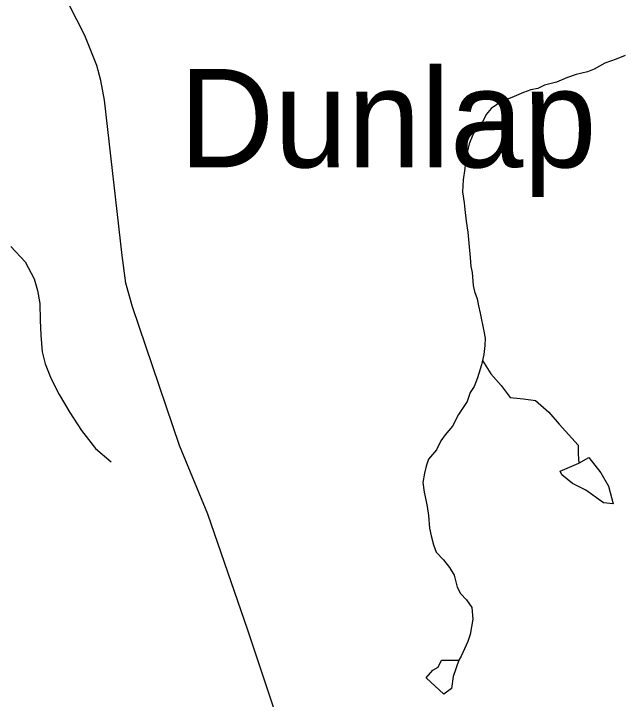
# Model space of a CAD drawing. Extents: x 0 to 34, y 0 to 22.
# Drawn here: x 2.892 to 3.382, y 19.73 to 20.28 of the extents above; entities that cross this region are included whole.
import ezdxf

# ---------------------------------------------------------------- set-up
doc = ezdxf.new("R2010")
doc.units = 0
for name, color, linetype in [('GM_X_County_Road', 7, 'Continuous'), ('GM_X_Minor_Lake', 7, 'Continuous'), ('GM_X_Minor_River', 7, 'Continuous'), ('GM_X_Unincorporated_Text', 7, 'Continuous')]:
    doc.layers.add(name, color=color, linetype=linetype)

msp = doc.modelspace()

# ---------------------------------------------------------------- linework, layer by layer
at = {"layer": 'GM_X_County_Road'}
msp.add_lwpolyline([(3.29284, 19.28987), (3.24187, 19.38373), (3.19405, 19.46941), (3.16152, 19.53179), (3.14395, 19.59345), (3.08002, 19.78523), (3.04799, 19.87833), (3.02524, 19.93351), (2.98757, 20.04453), (2.98244, 20.0637), (2.97932, 20.08578), (2.96513, 20.2103), (2.96238, 20.22608), (2.95906, 20.23808), (2.94936, 20.26224), (2.91043, 20.33888)], dxfattribs=at)
at = {"layer": 'GM_X_Minor_Lake'}
for points in [[(3.36531, 19.88758), (3.35109, 19.89775), (3.34055, 19.9029), (3.33196, 19.90992), (3.3305, 19.91299), (3.34538, 19.91923)], [(3.34538, 19.91923), (3.35352, 19.92392), (3.36315, 19.91156), (3.36938, 19.90079), (3.3729, 19.88666), (3.36531, 19.88758)], [(3.22299, 19.74723), (3.22843, 19.75319), (3.23267, 19.75577), (3.23544, 19.76141), (3.24939, 19.76137)], [(3.24939, 19.76137), (3.24467, 19.7483), (3.24333, 19.73845), (3.23716, 19.73401), (3.22299, 19.74723)]]:
    msp.add_lwpolyline(points, dxfattribs=at)
at = {"layer": 'GM_X_Minor_River'}
for points in [[(3.38269, 20.24614), (3.37542, 20.24324), (3.36625, 20.24), (3.3578, 20.23523), (3.35244, 20.23305), (3.34329, 20.23095), (3.3364, 20.22843), (3.3276, 20.2248), (3.31806, 20.22233), (3.31269, 20.21978), (3.30698, 20.21875), (3.30124, 20.21658), (3.29167, 20.21259), (3.28364, 20.20971), (3.27517, 20.20379), (3.27128, 20.19893), (3.2685, 20.19328), (3.26229, 20.18617), (3.25991, 20.18128), (3.25751, 20.17524), (3.25499, 20.1635), (3.25407, 20.15553), (3.25275, 20.14643), (3.25218, 20.13693), (3.25352, 20.12816), (3.25417, 20.12282), (3.25512, 20.11329), (3.25646, 20.10452), (3.25742, 20.09575), (3.25832, 20.08432), (3.25894, 20.07709), (3.25998, 20.07212), (3.26091, 20.06183), (3.26194, 20.05687), (3.2641, 20.05112), (3.26513, 20.04539), (3.26653, 20.03966), (3.26927, 20.02515), (3.27029, 20.01943), (3.27018, 20.01372), (3.26927, 20.00651), (3.26759, 19.99818), (3.26433, 19.9876), (3.26154, 19.98081), (3.2584, 19.97592), (3.25598, 19.96874), (3.24893, 19.95824), (3.24419, 19.94882), (3.23836, 19.94209), (3.23484, 19.93722), (3.23128, 19.93007), (3.22506, 19.92259), (3.22304, 19.91692)], [(2.89008, 20.09313), (2.90155, 20.08068), (2.90882, 20.0672), (2.91163, 20.05762), (2.91327, 20.04732), (2.91371, 20.034), (2.91418, 20.02181), (2.91538, 20.00848), (2.9178, 19.99891), (2.92245, 19.98701), (2.92898, 19.9743), (2.93736, 19.96003), (2.94688, 19.94535), (2.95792, 19.93101), (2.97057, 19.92044)], [(3.26828, 20.00163), (3.27504, 19.99101), (3.28335, 19.98151), (3.29047, 19.97202), (3.30115, 19.97083), (3.31065, 19.96964), (3.32134, 19.96014), (3.32965, 19.95064), (3.345, 19.93384), (3.345, 19.92639), (3.34538, 19.91923)], [(3.22304, 19.91692), (3.22179, 19.91124), (3.2205, 19.90366), (3.22148, 19.89603), (3.22288, 19.88992), (3.22391, 19.88457), (3.2249, 19.87733), (3.22583, 19.86704), (3.22722, 19.86093), (3.22897, 19.85366), (3.23113, 19.84791), (3.23708, 19.84171), (3.24189, 19.83553), (3.24556, 19.82937), (3.24803, 19.81981), (3.25058, 19.81482), (3.25541, 19.80978), (3.25984, 19.8036), (3.26041, 19.79408), (3.25953, 19.78801), (3.25826, 19.78195), (3.25663, 19.77628), (3.25385, 19.77025), (3.25108, 19.7646), (3.24939, 19.76137)]]:
    msp.add_lwpolyline(points, dxfattribs=at)

# ---------------------------------------------------------------- texts
at = {"layer": 'GM_X_Unincorporated_Text'}
msp.add_text('Dunlap', height=0.078977, rotation=0, dxfattribs=at).set_placement((3.02504, 20.15651))

doc.saveas('drawing.dxf')
